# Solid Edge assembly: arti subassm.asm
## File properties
Author: Deepak Maini
Template: Normal.asm
Last saved by: Robert a Rhodes jr
Revision: 14
Application: Solid Edge
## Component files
rod bush lower.par
rod bush upper.par
articulated rod.par
piston.par
piston pin.par
piston pin plug.par
piston ring.par
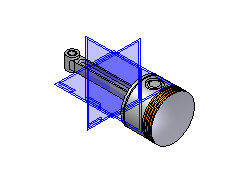
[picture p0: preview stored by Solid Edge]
